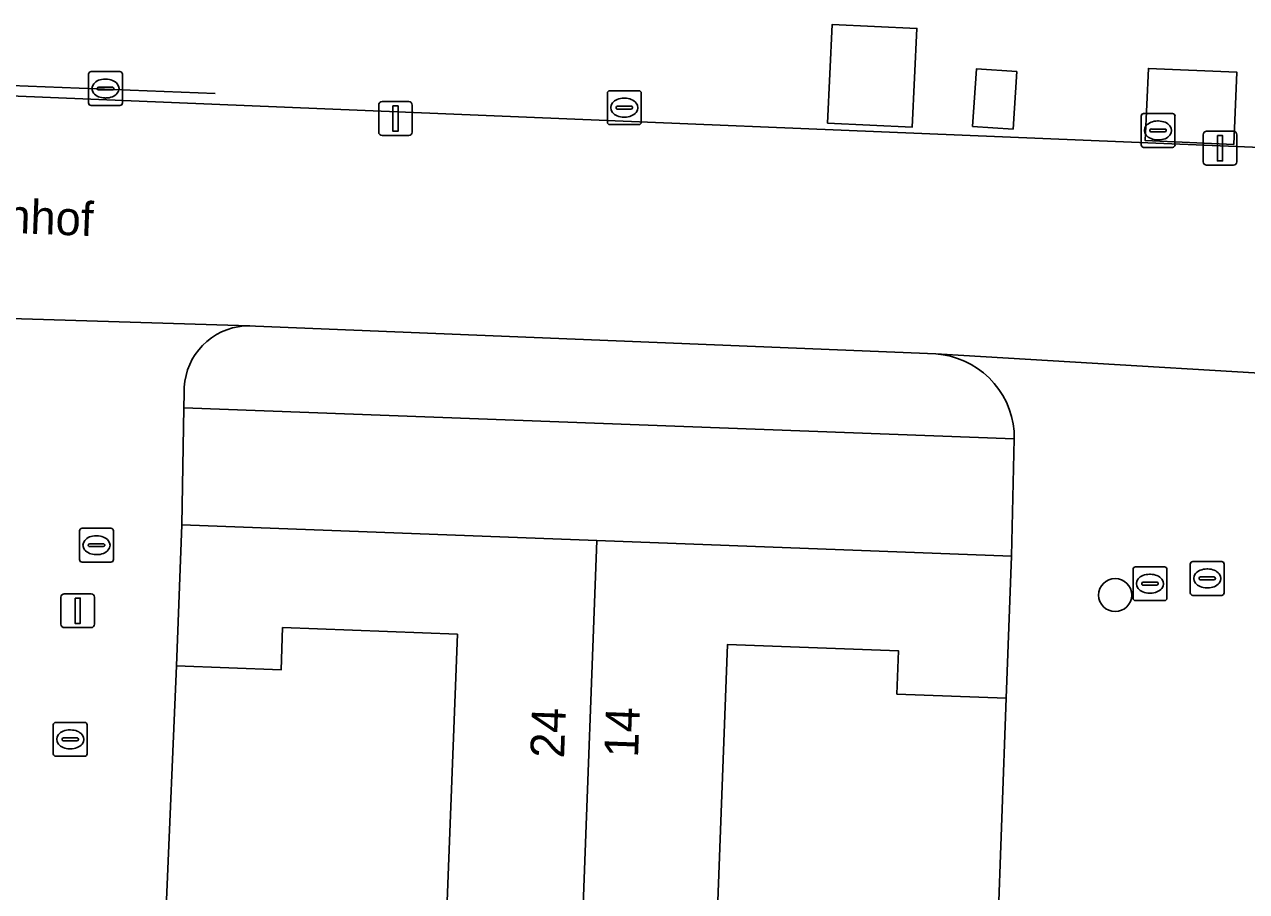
# Model space of a CAD drawing. Extents: x 160786 to 161429, y 386828 to 387485.
# Drawn here: x 161204.51 to 161240.63, y 387264.64 to 387290.27 of the extents above; entities that cross this region are included whole.
import ezdxf

# ---------------------------------------------------------------- set-up
doc = ezdxf.new("R2010")
doc.units = 0
for name, color, linetype in [('IMGEO_Boom', 7, 'Continuous'), ('IMGEO_Erf', 7, 'Continuous'), ('IMGEO_Groenvoorziening', 7, 'Continuous'), ('IMGEO_Kolk', 7, 'Continuous'), ('IMGEO_Lichtmast', 7, 'Continuous'), ('IMGEO_Muur', 7, 'Continuous'), ('IMGEO_Openbare_ruimte_label', 7, 'Continuous'), ('IMGEO_Pand', 7, 'Continuous'), ('IMGEO_Pand_nummerreeks', 7, 'Continuous'), ('IMGEO_Rioolput', 7, 'Continuous'), ('IMGEO_Voetpad_open', 7, 'Continuous')]:
    doc.layers.add(name, color=color, linetype=linetype)

msp = doc.modelspace()

# ---------------------------------------------------------------- linework, layer by layer
at = {"layer": 'IMGEO_Boom'}
msp.add_circle((161236.746, 387273.404), 0.489, dxfattribs=at)
at = {"layer": 'IMGEO_Erf'}
for points in [[(161230.886, 387290.151), (161230.75, 387287.235), (161228.246, 387287.352), (161228.383, 387290.268)], [(161232.644, 387288.954), (161233.839, 387288.875), (161233.727, 387287.175), (161232.532, 387287.253)], [(161237.731, 387288.967), (161240.346, 387288.853), (161240.253, 387286.722), (161237.638, 387286.836)], [(161208.693, 387264.163), (161216.986, 387263.847), (161217.307, 387272.247), (161212.139, 387272.444), (161212.092, 387271.194), (161209, 387271.312)], [(161233.524, 387270.355), (161230.298, 387270.478), (161230.346, 387271.753), (161225.29, 387271.946), (161224.971, 387263.578), (161233.272, 387263.261)]]:
    msp.add_lwpolyline(points, close=True, dxfattribs=at)
msp.add_lwpolyline([(161170.163, 387289.466), (161204.081, 387288.161), (161247.486, 387286.367), (161267.914, 387285.628)], dxfattribs=at)
at = {"layer": 'IMGEO_Groenvoorziening'}
for points in [[(161233.764, 387278.025), (161233.757, 387278.247), (161233.73, 387278.467), (161233.683, 387278.684), (161233.617, 387278.895), (161233.533, 387279.101), (161233.43, 387279.297), (161233.311, 387279.484), (161233.175, 387279.659), (161233.024, 387279.822), (161232.859, 387279.97), (161232.681, 387280.103), (161232.493, 387280.22), (161232.294, 387280.319), (161232.088, 387280.4), (161231.875, 387280.463), (161231.658, 387280.506), (161231.449, 387280.529), (161211.335, 387281.354), (161211.164, 387281.363), (161210.992, 387281.357), (161210.822, 387281.335), (161210.654, 387281.298), (161210.49, 387281.246), (161210.332, 387281.18), (161210.18, 387281.1), (161210.036, 387281.007), (161209.9, 387280.901), (161209.775, 387280.784), (161209.661, 387280.656), (161209.558, 387280.518), (161209.469, 387280.371), (161209.392, 387280.217), (161209.33, 387280.057), (161209.283, 387279.892), (161209.25, 387279.724), (161209.232, 387279.553), (161209.23, 387279.381), (161209.231, 387279.359), (161209.223, 387278.939)], [(161233.684, 387274.549), (161233.764, 387278.025), (161209.223, 387278.939), (161209.159, 387275.484), (161221.422, 387275.016)]]:
    msp.add_lwpolyline(points, close=True, dxfattribs=at)
at = {"layer": 'IMGEO_Kolk'}
for p, q in [((161206.402, 387287.948), (161206.402, 387288.8)), ((161206.477, 387288.874), (161207.329, 387288.874)), ((161207.403, 387288.8), (161207.403, 387287.948)), ((161206.661, 387288.368), (161206.661, 387288.38)), ((161206.704, 387288.417), (161207.102, 387288.417)), ((161206.89, 387288.654), (161206.915, 387288.654)), ((161207.145, 387288.38), (161207.145, 387288.368)), ((161207.099, 387288.331), (161206.701, 387288.331)), ((161206.913, 387288.094), (161206.888, 387288.094)), ((161221.737, 387287.382), (161221.737, 387288.234)), ((161221.812, 387288.308), (161222.664, 387288.308)), ((161222.225, 387288.088), (161222.25, 387288.088)), ((161222.738, 387288.234), (161222.738, 387287.382)), ((161207.329, 387287.874), (161206.477, 387287.874)), ((161221.996, 387287.802), (161221.996, 387287.814)), ((161222.434, 387287.765), (161222.036, 387287.765)), ((161222.039, 387287.851), (161222.437, 387287.851)), ((161222.48, 387287.814), (161222.48, 387287.802)), ((161237.589, 387287.635), (161238.441, 387287.635)), ((161222.664, 387287.308), (161221.812, 387287.308)), ((161222.248, 387287.528), (161222.223, 387287.528)), ((161237.514, 387286.709), (161237.514, 387287.561)), ((161238.002, 387287.415), (161238.027, 387287.415)), ((161238.515, 387287.561), (161238.515, 387286.709)), ((161237.773, 387287.129), (161237.773, 387287.141)), ((161238.211, 387287.092), (161237.813, 387287.092)), ((161237.816, 387287.178), (161238.214, 387287.178)), ((161238.257, 387287.141), (161238.257, 387287.129)), ((161238.441, 387286.635), (161237.589, 387286.635)), ((161238.025, 387286.855), (161238, 387286.855)), ((161238.968, 387273.469), (161238.968, 387274.321)), ((161239.043, 387274.395), (161239.895, 387274.395)), ((161239.969, 387274.321), (161239.969, 387273.469)), ((161239.27, 387273.938), (161239.668, 387273.938)), ((161239.456, 387274.175), (161239.481, 387274.175)), ((161239.227, 387273.889), (161239.227, 387273.901)), ((161239.665, 387273.852), (161239.267, 387273.852)), ((161239.479, 387273.615), (161239.454, 387273.615)), ((161239.711, 387273.901), (161239.711, 387273.889)), ((161239.895, 387273.395), (161239.043, 387273.395)), ((161205.435, 387269.639), (161206.287, 387269.639)), ((161205.36, 387268.713), (161205.36, 387269.565)), ((161205.848, 387269.419), (161205.873, 387269.419)), ((161206.361, 387269.565), (161206.361, 387268.713)), ((161205.619, 387269.133), (161205.619, 387269.145)), ((161206.057, 387269.096), (161205.659, 387269.096)), ((161205.662, 387269.182), (161206.06, 387269.182)), ((161205.871, 387268.859), (161205.846, 387268.859)), ((161206.103, 387269.145), (161206.103, 387269.133)), ((161206.287, 387268.639), (161205.435, 387268.639))]:
    msp.add_line(p, q, dxfattribs=at)
for points in [[(161206.402, 387287.948), (161206.402, 387288.8)], [(161206.477, 387288.874), (161207.329, 387288.874)], [(161207.403, 387288.8), (161207.403, 387287.948)], [(161221.737, 387287.382), (161221.737, 387288.234)], [(161221.812, 387288.308), (161222.664, 387288.308)], [(161222.738, 387288.234), (161222.738, 387287.382)], [(161207.329, 387287.874), (161206.477, 387287.874)], [(161237.589, 387287.635), (161238.441, 387287.635)], [(161222.664, 387287.308), (161221.812, 387287.308)], [(161237.514, 387286.709), (161237.514, 387287.561)], [(161238.515, 387287.561), (161238.515, 387286.709)], [(161238.441, 387286.635), (161237.589, 387286.635)], [(161238.968, 387273.469), (161238.968, 387274.321)], [(161239.043, 387274.395), (161239.895, 387274.395)], [(161239.969, 387274.321), (161239.969, 387273.469)], [(161239.895, 387273.395), (161239.043, 387273.395)], [(161205.435, 387269.639), (161206.287, 387269.639)], [(161205.36, 387268.713), (161205.36, 387269.565)], [(161206.361, 387269.565), (161206.361, 387268.713)], [(161206.287, 387268.639), (161205.435, 387268.639)]]:
    msp.add_lwpolyline(points, dxfattribs=at)
for centre, radius, start, end in [((161206.479, 387288.798), 0.0765, 91.552, 178.448), ((161206.479, 387288.798), 0.0765, 91.552, 178.448), ((161207.327, 387288.798), 0.0765, 1.552, 88.448), ((161207.327, 387288.798), 0.0765, 1.552, 88.448), ((161206.701, 387288.377), 0.0403, 85.8775, 175.7526), ((161206.698, 387288.367), 0.0366, 178.938, 274.7102), ((161207.102, 387288.374), 0.043, 264.8664, 352.4533), ((161207.106, 387288.379), 0.0386, 1.7309, 96.639), ((161221.814, 387288.232), 0.0765, 91.552, 178.448), ((161221.814, 387288.232), 0.0765, 91.552, 178.448), ((161222.662, 387288.232), 0.0765, 1.552, 88.448), ((161222.662, 387288.232), 0.0765, 1.552, 88.448), ((161206.479, 387287.95), 0.0765, 181.552, 268.448), ((161206.479, 387287.95), 0.0765, 181.552, 268.448), ((161207.327, 387287.95), 0.0765, 271.552, 358.448), ((161207.327, 387287.95), 0.0765, 271.552, 358.448), ((161222.036, 387287.811), 0.0403, 85.8775, 175.7526), ((161222.033, 387287.801), 0.0366, 178.938, 274.7102), ((161222.437, 387287.808), 0.043, 264.8664, 352.4533), ((161222.441, 387287.813), 0.0386, 1.7309, 96.639), ((161237.591, 387287.559), 0.0765, 91.552, 178.448), ((161237.591, 387287.559), 0.0765, 91.552, 178.448), ((161238.439, 387287.559), 0.0765, 1.552, 88.448), ((161238.439, 387287.559), 0.0765, 1.552, 88.448), ((161221.814, 387287.384), 0.0765, 181.552, 268.448), ((161221.814, 387287.384), 0.0765, 181.552, 268.448), ((161222.662, 387287.384), 0.0765, 271.552, 358.448), ((161222.662, 387287.384), 0.0765, 271.552, 358.448), ((161237.813, 387287.138), 0.0403, 85.8775, 175.7526), ((161237.81, 387287.128), 0.0366, 178.938, 274.7102), ((161238.214, 387287.135), 0.043, 264.8664, 352.4533), ((161238.218, 387287.14), 0.0386, 1.7309, 96.639), ((161237.591, 387286.711), 0.0765, 181.552, 268.448), ((161237.591, 387286.711), 0.0765, 181.552, 268.448), ((161238.439, 387286.711), 0.0765, 271.552, 358.448), ((161238.439, 387286.711), 0.0765, 271.552, 358.448), ((161239.045, 387274.319), 0.0765, 91.552, 178.448), ((161239.045, 387274.319), 0.0765, 91.552, 178.448), ((161239.893, 387274.319), 0.0765, 1.552, 88.448), ((161239.893, 387274.319), 0.0765, 1.552, 88.448), ((161239.267, 387273.898), 0.0403, 85.8775, 175.7526), ((161239.672, 387273.9), 0.0386, 1.7309, 96.639), ((161239.264, 387273.888), 0.0366, 178.938, 274.7102), ((161239.668, 387273.895), 0.043, 264.8664, 352.4533), ((161239.045, 387273.471), 0.0765, 181.552, 268.448), ((161239.045, 387273.471), 0.0765, 181.552, 268.448), ((161239.893, 387273.471), 0.0765, 271.552, 358.448), ((161239.893, 387273.471), 0.0765, 271.552, 358.448), ((161205.437, 387269.563), 0.0765, 91.552, 178.448), ((161205.437, 387269.563), 0.0765, 91.552, 178.448), ((161206.285, 387269.563), 0.0765, 1.552, 88.448), ((161206.285, 387269.563), 0.0765, 1.552, 88.448), ((161205.659, 387269.142), 0.0403, 85.8775, 175.7526), ((161205.656, 387269.132), 0.0366, 178.938, 274.7102), ((161206.06, 387269.139), 0.043, 264.8664, 352.4533), ((161206.064, 387269.144), 0.0386, 1.7309, 96.639), ((161205.437, 387268.715), 0.0765, 181.552, 268.448), ((161205.437, 387268.715), 0.0765, 181.552, 268.448), ((161206.285, 387268.715), 0.0765, 271.552, 358.448), ((161206.285, 387268.715), 0.0765, 271.552, 358.448)]:
    msp.add_arc(centre, radius, start, end, dxfattribs=at)
for centre, major_axis, ratio, start_param, end_param in [((161206.889, 387288.374), (-0.387, 0.002), 0.722429, 4.712389, 7.853982), ((161206.914, 387288.374), (-0.39, 0.002), 0.717154, 1.570796, 4.712389), ((161222.224, 387287.808), (-0.387, 0.002), 0.722429, 4.712389, 7.853982), ((161222.249, 387287.808), (-0.39, 0.002), 0.717154, 1.570796, 4.712389), ((161238.001, 387287.135), (-0.387, 0.002), 0.722429, 4.712389, 7.853982), ((161238.026, 387287.135), (-0.39, 0.002), 0.717154, 1.570796, 4.712389), ((161239.455, 387273.895), (-0.387, 0.002), 0.722429, 4.712389, 7.853982), ((161239.48, 387273.895), (-0.39, 0.002), 0.717154, 1.570796, 4.712389), ((161205.847, 387269.139), (-0.387, 0.002), 0.722429, 4.712389, 7.853982), ((161205.872, 387269.139), (-0.39, 0.002), 0.717154, 1.570796, 4.712389)]:
    msp.add_ellipse(centre, major_axis=major_axis, ratio=ratio, start_param=start_param, end_param=end_param, dxfattribs=at)
at = {"layer": 'IMGEO_Lichtmast'}
for p, q in [((161214.979, 387287.087), (161214.979, 387287.887)), ((161214.979, 387287.887), (161214.979, 387287.087)), ((161215.079, 387287.987), (161215.869, 387287.987)), ((161215.869, 387287.987), (161215.079, 387287.987)), ((161215.969, 387287.887), (161215.969, 387287.087)), ((161215.969, 387287.087), (161215.969, 387287.887)), ((161215.869, 387286.987), (161215.079, 387286.987)), ((161215.079, 387286.987), (161215.869, 387286.987)), ((161239.351, 387286.21), (161239.351, 387287.01)), ((161239.351, 387287.01), (161239.351, 387286.21)), ((161239.451, 387287.11), (161240.241, 387287.11)), ((161240.241, 387287.11), (161239.451, 387287.11)), ((161240.341, 387287.01), (161240.341, 387286.21)), ((161240.341, 387286.21), (161240.341, 387287.01)), ((161240.241, 387286.11), (161239.451, 387286.11)), ((161239.451, 387286.11), (161240.241, 387286.11)), ((161205.586, 387272.542), (161205.586, 387273.342)), ((161205.586, 387273.342), (161205.586, 387272.542)), ((161205.686, 387273.442), (161206.476, 387273.442)), ((161206.476, 387273.442), (161205.686, 387273.442)), ((161206.576, 387273.342), (161206.576, 387272.542)), ((161206.576, 387272.542), (161206.576, 387273.342)), ((161206.476, 387272.442), (161205.686, 387272.442)), ((161205.686, 387272.442), (161206.476, 387272.442))]:
    msp.add_line(p, q, dxfattribs=at)
for points in [[(161215.399, 387287.862), (161215.549, 387287.862), (161215.549, 387287.112), (161215.399, 387287.112), (161215.399, 387287.862)], [(161239.771, 387286.985), (161239.921, 387286.985), (161239.921, 387286.235), (161239.771, 387286.235), (161239.771, 387286.985)], [(161206.006, 387273.317), (161206.156, 387273.317), (161206.156, 387272.567), (161206.006, 387272.567), (161206.006, 387273.317)]]:
    msp.add_lwpolyline(points, dxfattribs=at)
for centre, start, end in [((161215.079, 387287.887), 90, 180), ((161215.079, 387287.887), 90, 180), ((161215.869, 387287.887), 0, 90), ((161215.869, 387287.887), 360, 90), ((161215.079, 387287.087), 180, 270), ((161215.079, 387287.087), 180, 270), ((161215.869, 387287.087), 270, 0), ((161215.869, 387287.087), 270, 0), ((161239.451, 387287.01), 90, 180), ((161239.451, 387287.01), 90, 180), ((161240.241, 387287.01), 0, 90), ((161240.241, 387287.01), 360, 90), ((161239.451, 387286.21), 180, 270), ((161239.451, 387286.21), 180, 270), ((161240.241, 387286.21), 270, 0), ((161240.241, 387286.21), 270, 0), ((161205.686, 387273.342), 90, 180), ((161205.686, 387273.342), 90, 180), ((161206.476, 387273.342), 0, 90), ((161206.476, 387273.342), 360, 90), ((161205.686, 387272.542), 180, 270), ((161205.686, 387272.542), 180, 270), ((161206.476, 387272.542), 270, 0), ((161206.476, 387272.542), 270, 0)]:
    msp.add_arc(centre, 0.1, start, end, dxfattribs=at)
at = {"layer": 'IMGEO_Muur'}
for points in [[(161210.144, 387288.23), (161204.119, 387288.468)], [(161209, 387271.312), (161208.693, 387264.163)], [(161233.272, 387263.261), (161233.524, 387270.355)]]:
    msp.add_lwpolyline(points, dxfattribs=at)
at = {"layer": 'IMGEO_Pand'}
for points in [[(161228.246, 387287.352), (161230.75, 387287.235), (161230.886, 387290.151), (161228.383, 387290.268)], [(161232.532, 387287.253), (161233.727, 387287.175), (161233.839, 387288.875), (161232.644, 387288.954)], [(161237.638, 387286.836), (161240.253, 387286.722), (161240.346, 387288.853), (161237.731, 387288.967)], [(161209, 387271.312), (161212.092, 387271.194), (161212.139, 387272.444), (161217.307, 387272.247), (161216.986, 387263.847), (161221.001, 387263.712), (161221.422, 387275.016), (161209.159, 387275.484)], [(161233.684, 387274.549), (161221.422, 387275.016), (161221.001, 387263.712), (161224.971, 387263.578), (161225.29, 387271.946), (161230.346, 387271.753), (161230.298, 387270.478), (161233.524, 387270.355)]]:
    msp.add_lwpolyline(points, close=True, dxfattribs=at)
at = {"layer": 'IMGEO_Rioolput'}
for p, q in [((161206.211, 387275.378), (161207.063, 387275.378)), ((161206.136, 387274.452), (161206.136, 387275.304)), ((161206.624, 387275.158), (161206.649, 387275.158)), ((161207.137, 387275.304), (161207.137, 387274.452)), ((161206.395, 387274.872), (161206.395, 387274.884)), ((161206.833, 387274.835), (161206.435, 387274.835)), ((161206.438, 387274.921), (161206.836, 387274.921)), ((161206.879, 387274.884), (161206.879, 387274.872)), ((161207.063, 387274.378), (161206.211, 387274.378)), ((161206.647, 387274.598), (161206.622, 387274.598)), ((161237.274, 387273.313), (161237.274, 387274.165)), ((161237.349, 387274.239), (161238.201, 387274.239)), ((161237.762, 387274.019), (161237.787, 387274.019)), ((161238.275, 387274.165), (161238.275, 387273.313)), ((161237.533, 387273.733), (161237.533, 387273.745)), ((161237.971, 387273.696), (161237.573, 387273.696)), ((161237.576, 387273.782), (161237.974, 387273.782)), ((161238.017, 387273.745), (161238.017, 387273.733)), ((161238.201, 387273.239), (161237.349, 387273.239)), ((161237.785, 387273.459), (161237.76, 387273.459))]:
    msp.add_line(p, q, dxfattribs=at)
for points in [[(161206.211, 387275.378), (161207.063, 387275.378)], [(161206.136, 387274.452), (161206.136, 387275.304)], [(161207.137, 387275.304), (161207.137, 387274.452)], [(161207.063, 387274.378), (161206.211, 387274.378)], [(161237.274, 387273.313), (161237.274, 387274.165)], [(161237.349, 387274.239), (161238.201, 387274.239)], [(161238.275, 387274.165), (161238.275, 387273.313)], [(161238.201, 387273.239), (161237.349, 387273.239)]]:
    msp.add_lwpolyline(points, dxfattribs=at)
for centre, radius, start, end in [((161206.213, 387275.302), 0.0765, 91.552, 178.448), ((161206.213, 387275.302), 0.0765, 91.552, 178.448), ((161207.061, 387275.302), 0.0765, 1.552, 88.448), ((161207.061, 387275.302), 0.0765, 1.552, 88.448), ((161206.435, 387274.881), 0.0403, 85.8775, 175.7526), ((161206.432, 387274.871), 0.0366, 178.938, 274.7102), ((161206.836, 387274.878), 0.043, 264.8664, 352.4533), ((161206.84, 387274.883), 0.0386, 1.7309, 96.639), ((161206.213, 387274.454), 0.0765, 181.552, 268.448), ((161206.213, 387274.454), 0.0765, 181.552, 268.448), ((161207.061, 387274.454), 0.0765, 271.552, 358.448), ((161207.061, 387274.454), 0.0765, 271.552, 358.448), ((161237.351, 387274.163), 0.0765, 91.552, 178.448), ((161237.351, 387274.163), 0.0765, 91.552, 178.448), ((161238.199, 387274.163), 0.0765, 1.552, 88.448), ((161238.199, 387274.163), 0.0765, 1.552, 88.448), ((161237.573, 387273.742), 0.0403, 85.8775, 175.7526), ((161237.57, 387273.732), 0.0366, 178.938, 274.7102), ((161237.974, 387273.739), 0.043, 264.8664, 352.4533), ((161237.978, 387273.744), 0.0386, 1.7309, 96.639), ((161237.351, 387273.315), 0.0765, 181.552, 268.448), ((161237.351, 387273.315), 0.0765, 181.552, 268.448), ((161238.199, 387273.315), 0.0765, 271.552, 358.448), ((161238.199, 387273.315), 0.0765, 271.552, 358.448)]:
    msp.add_arc(centre, radius, start, end, dxfattribs=at)
for centre, major_axis, ratio, start_param, end_param in [((161206.623, 387274.878), (-0.387, 0.002), 0.722429, 4.712389, 7.853982), ((161206.648, 387274.878), (-0.39, 0.002), 0.717154, 1.570796, 4.712389), ((161237.761, 387273.739), (-0.387, 0.002), 0.722429, 4.712389, 7.853982), ((161237.786, 387273.739), (-0.39, 0.002), 0.717154, 1.570796, 4.712389)]:
    msp.add_ellipse(centre, major_axis=major_axis, ratio=ratio, start_param=start_param, end_param=end_param, dxfattribs=at)
at = {"layer": 'IMGEO_Voetpad_open'}
for points in [[(161247.486, 387286.367), (161204.081, 387288.161), (161170.163, 387289.466), (161164.829, 387289.6), (161164.69, 387286.821)], [(161138.578, 387288.383), (161137.745, 387283.796), (161143.258, 387283.56), (161169.71, 387282.428), (161181.145, 387282.379), (161181.317, 387282.373), (161201.652, 387281.657), (161201.851, 387281.648), (161211.164, 387281.363), (161211.335, 387281.354), (161231.449, 387280.529), (161245.64, 387279.689), (161245.804, 387283.807), (161258.09, 387283.318), (161270.377, 387282.829), (161270.534, 387287.689)], [(161208.693, 387264.163), (161209, 387271.312), (161209.159, 387275.484), (161209.223, 387278.939), (161209.231, 387279.359), (161209.23, 387279.381), (161209.232, 387279.553), (161209.25, 387279.724), (161209.283, 387279.892), (161209.33, 387280.057), (161209.392, 387280.217), (161209.469, 387280.371), (161209.558, 387280.518), (161209.661, 387280.656), (161209.775, 387280.784), (161209.9, 387280.901), (161210.036, 387281.007), (161210.18, 387281.1), (161210.332, 387281.18), (161210.49, 387281.246), (161210.654, 387281.298), (161210.822, 387281.335), (161210.992, 387281.357), (161211.164, 387281.363), (161201.851, 387281.648)], [(161245.64, 387279.689), (161231.449, 387280.529), (161231.658, 387280.506), (161231.875, 387280.463), (161232.088, 387280.4), (161232.294, 387280.319), (161232.493, 387280.22), (161232.681, 387280.103), (161232.859, 387279.97), (161233.024, 387279.822), (161233.175, 387279.659), (161233.311, 387279.484), (161233.43, 387279.297), (161233.533, 387279.101), (161233.617, 387278.895), (161233.683, 387278.684), (161233.73, 387278.467), (161233.757, 387278.247), (161233.764, 387278.025), (161233.684, 387274.549), (161233.524, 387270.355), (161233.272, 387263.261)]]:
    msp.add_lwpolyline(points, dxfattribs=at)

# ---------------------------------------------------------------- texts
at = {"layer": 'IMGEO_Openbare_ruimte_label'}
msp.add_text('Hosingenhof', height=1, rotation=357.7644, dxfattribs=at).set_placement((161199.024, 387284.305))
at = {"layer": 'IMGEO_Pand_nummerreeks'}
for s, rotation, p in [('24', 87.8716, (161220.456, 387268.572)), ('14', 87.8337, (161222.642, 387268.589))]:
    msp.add_text(s, height=1, rotation=rotation, dxfattribs=at).set_placement(p)

doc.saveas('drawing.dxf')
